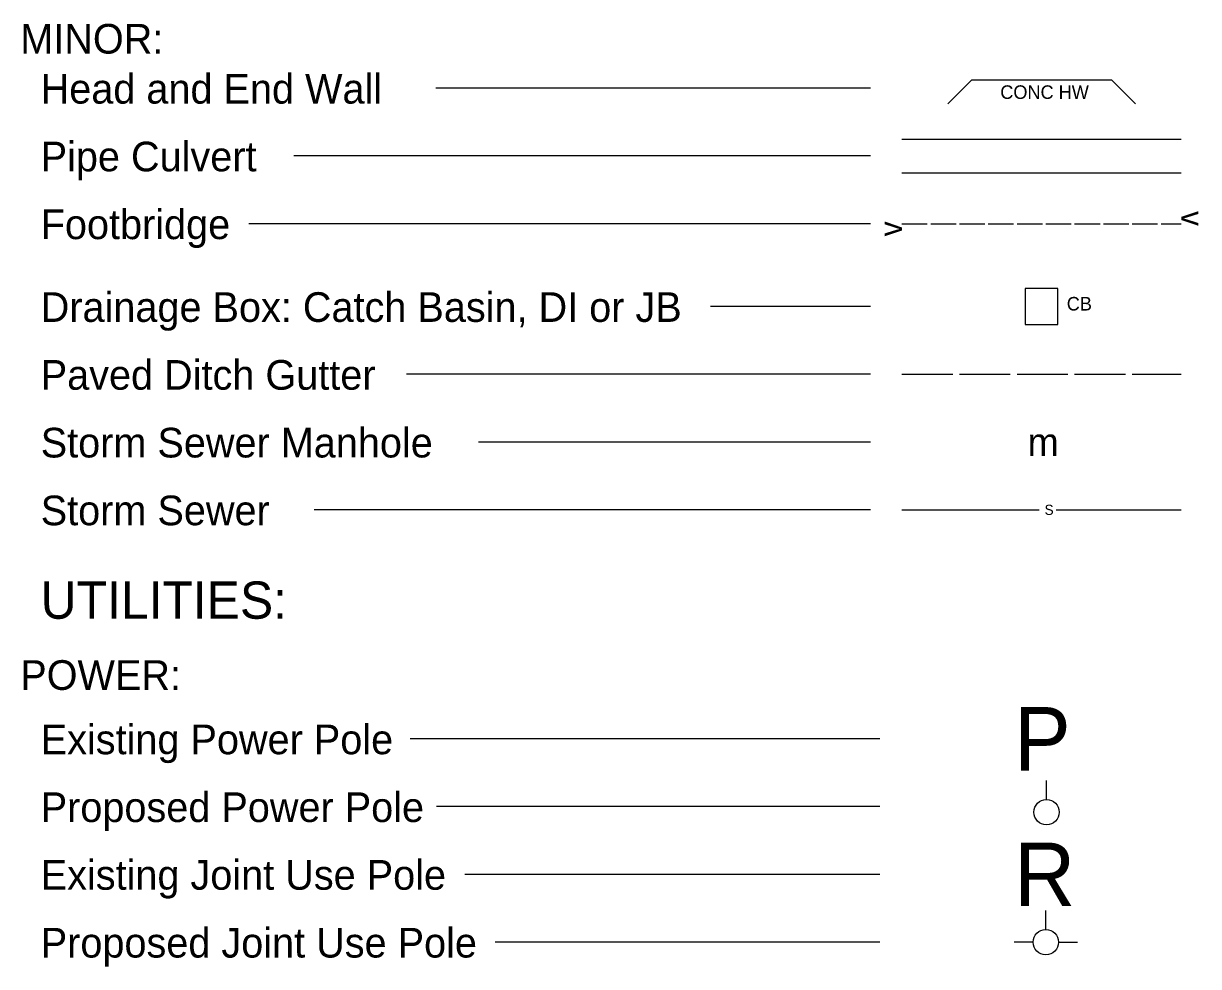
# Model space of a CAD drawing. Extents: x 1729964 to 1731648, y 539487 to 540587.
# Drawn here: x 1730894.4 to 1731241.4, y 540024.8 to 540303.1 of the extents above; entities that cross this region are included whole.
import ezdxf

# ---------------------------------------------------------------- set-up
doc = ezdxf.new("R2010")
doc.units = 0
doc.layers.add('Sheet Symbology CELL', color=7, linetype='Continuous')

msp = doc.modelspace()

# ---------------------------------------------------------------- linework, layer by layer
at = {"layer": 'Sheet Symbology CELL'}
for p, q in [((1731167.33, 540279.44), (1731174.4, 540286.52)), ((1731174.4, 540286.52), (1731215.65, 540286.52)), ((1731215.65, 540286.52), (1731222.73, 540279.44)), ((1731144.48, 540284.02), (1731016.18, 540284.02)), ((1731153.78, 540269.02), (1731236.28, 540269.02)), ((1731144.48, 540264.02), (1730974.29, 540264.02)), ((1731153.78, 540259.02), (1731236.28, 540259.02)), ((1731144.48, 540244.02), (1730961, 540244.02)), ((1731153.78, 540244.02), (1731161.28, 540244.02)), ((1731162.28, 540244.02), (1731169.78, 540244.02)), ((1731170.78, 540244.02), (1731178.28, 540244.02)), ((1731179.28, 540244.02), (1731186.78, 540244.02)), ((1731187.78, 540244.02), (1731195.28, 540244.02)), ((1731196.28, 540244.02), (1731203.78, 540244.02)), ((1731204.78, 540244.02), (1731212.28, 540244.02)), ((1731213.28, 540244.02), (1731220.78, 540244.02)), ((1731221.78, 540244.02), (1731229.28, 540244.02)), ((1731230.28, 540244.02), (1731236.28, 540244.02)), ((1731144.48, 540219.59), (1731097.28, 540219.59)), ((1731144.48, 540199.59), (1731007.53, 540199.59)), ((1731153.78, 540199.59), (1731168.78, 540199.59)), ((1731170.78, 540199.59), (1731185.78, 540199.59)), ((1731187.78, 540199.59), (1731202.78, 540199.59)), ((1731204.78, 540199.59), (1731219.78, 540199.59)), ((1731221.78, 540199.59), (1731236.28, 540199.59)), ((1731144.48, 540179.59), (1731028.8, 540179.59)), ((1731144.48, 540159.59), (1730980.28, 540159.59)), ((1731153.78, 540159.59), (1731194.3, 540159.59)), ((1731199.3, 540159.59), (1731236.28, 540159.59)), ((1731147.26, 540092), (1731008.56, 540092)), ((1731196.49, 540074.11), (1731196.49, 540079.74)), ((1731147.26, 540072), (1731016.35, 540072)), ((1731147.26, 540052), (1731024.75, 540052)), ((1731196.28, 540035.76), (1731196.28, 540041.39)), ((1731147.26, 540032), (1731033.75, 540032)), ((1731192.53, 540032.01), (1731186.9, 540032.01)), ((1731200.03, 540032.01), (1731205.65, 540032.01))]:
    msp.add_line(p, q, dxfattribs=at)
msp.add_lwpolyline([(1731190.21, 540214.28), (1731199.83, 540214.28), (1731199.83, 540224.91), (1731190.21, 540224.91)], close=True, dxfattribs=at)
for centre in [(1731196.49, 540070.36), (1731196.28, 540032)]:
    msp.add_circle(centre, 3.75, dxfattribs=at)

# ---------------------------------------------------------------- texts
for s, height, p in [('MINOR:', 8.75, (1730893.49, 540294.23)), ('Head and End Wall', 8.75, (1730899.51, 540279.47)), ('Pipe Culvert', 8.75, (1730899.51, 540259.48)), ('Footbridge', 8.75, (1730899.53, 540239.48)), ('Drainage Box: Catch Basin, DI or JB', 8.75, (1730899.53, 540215.05)), ('Paved Ditch Gutter', 8.75, (1730899.53, 540195.04)), ('Storm Sewer Manhole', 8.75, (1730899.53, 540175.04)), ('m', 8.25, (1731190.9, 540175.46)), ('Storm Sewer', 8.75, (1730899.53, 540155.04)), ('S', 3, (1731195.9, 540158.09)), ('UTILITIES:', 11, (1730899.51, 540127.45)), ('POWER:', 8.75, (1730893.49, 540106.46)), ('P', 18.75, (1731186.9, 540082.63)), ('Existing Power Pole', 8.75, (1730899.53, 540087.46)), ('Proposed Power Pole', 8.75, (1730899.53, 540067.46)), ('R', 18.75, (1731186.9, 540042.63)), ('Existing Joint Use Pole', 8.75, (1730899.53, 540047.48)), ('Proposed Joint Use Pole', 8.75, (1730899.54, 540027.46))]:
    msp.add_text(s, height=height, dxfattribs=at).set_placement(p)
for s, height, rotation, p in [('CONC HW', 4, 360, (1731182.83, 540280.86)), ('v', 6.6, 270.2409, (1731236.26, 540247.76)), ('v', 6.6, 89.7591, (1731153.76, 540240.28)), ('CB', 4, 360, (1731202.46, 540218.41))]:
    msp.add_text(s, height=height, rotation=rotation, dxfattribs=at).set_placement(p)

doc.saveas('drawing.dxf')
